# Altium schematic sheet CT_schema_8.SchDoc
size 277 x 170 mm
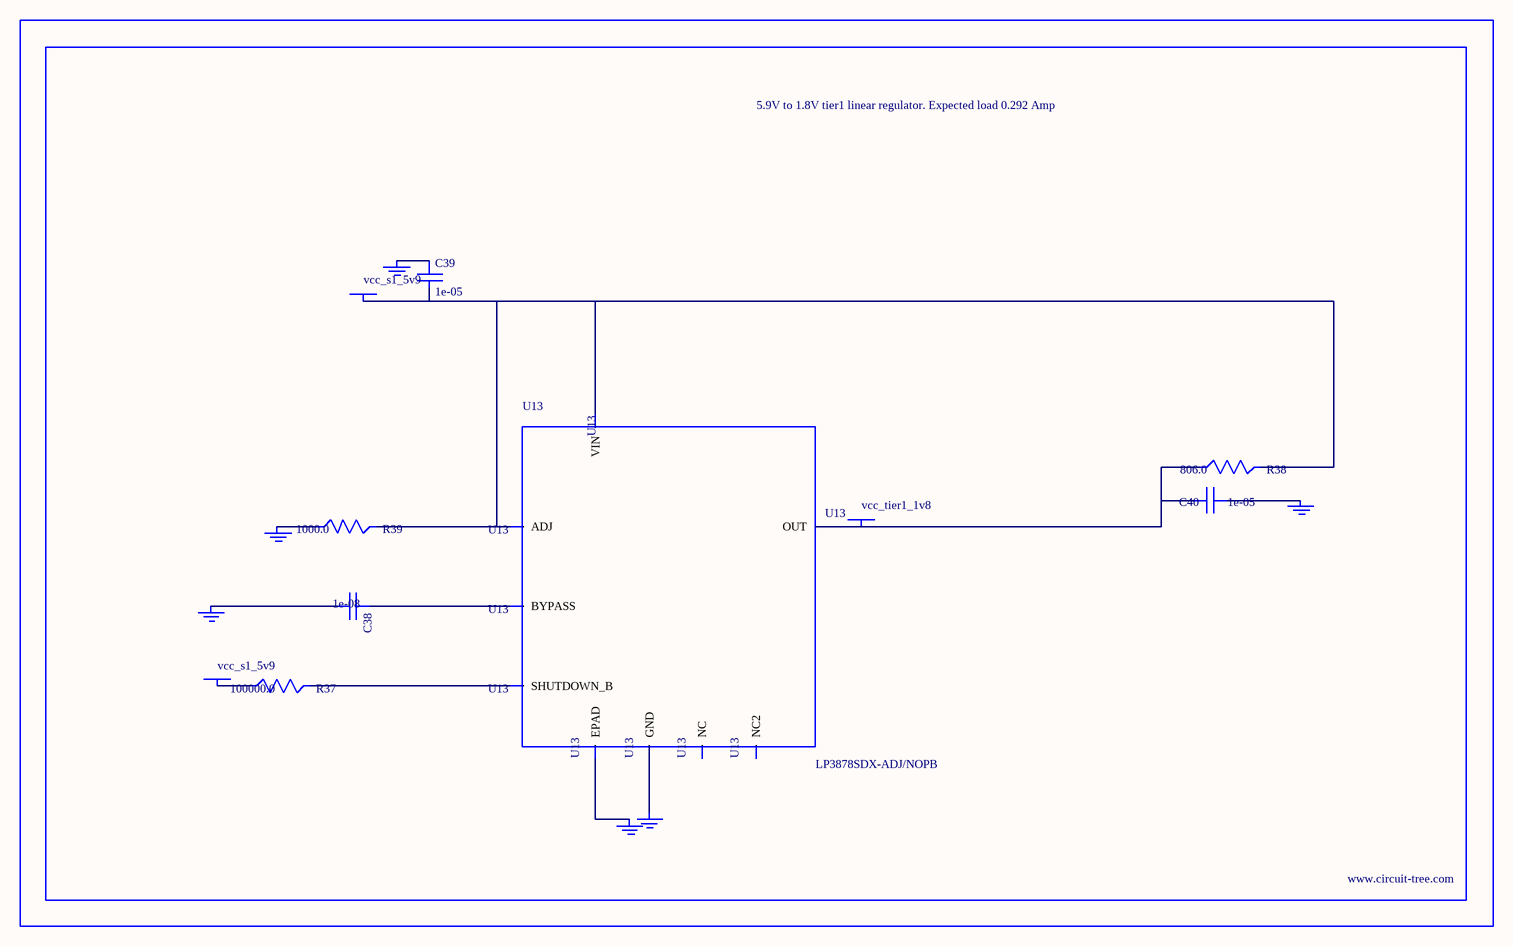
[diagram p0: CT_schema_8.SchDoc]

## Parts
BORDER7  (no value)
C38  1e-08  [C0402]
C39  1e-05  [C1206]
C40  1e-05  [C0805]
GND_INSTANCE_7_0  (no value)
GND_INSTANCE_7_1  (no value)
GND_INSTANCE_7_2  (no value)
GND_INSTANCE_7_3  (no value)
GND_INSTANCE_7_4  (no value)
GND_INSTANCE_7_5  (no value)
POWER_INSTANCE_7_0  vcc_s1_5v9
POWER_INSTANCE_7_1  vcc_s1_5v9
POWER_INSTANCE_7_2  vcc_tier1_1v8
R37  100000.0  [R0603]
R38  806.0  [R0603]
R39  1000.0  [R0603]
U13  LP3878SDX-ADJ/NOPB  [WSON-8]

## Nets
NetC38_1: C38.1 U13.1(BYPASS)
NetC38_2: C38.2 GND_INSTANCE_7_0.0(GND)
NetC39_1: C39.1 GND_INSTANCE_7_1.0(GND)
NetC39_2: C39.2 POWER_INSTANCE_7_0.0(PWR) R38.2 R39.2 U13.4(VIN) U13.6(ADJ)
NetC40_1: C40.1 GND_INSTANCE_7_2.0(GND)
NetC40_2: C40.2 POWER_INSTANCE_7_2.0(PWR) R38.1 U13.5(OUT)
NetGND_INSTANCE_7_3_0: GND_INSTANCE_7_3.0(GND) R39.1
NetGND_INSTANCE_7_4_0: GND_INSTANCE_7_4.0(GND) U13.PAD(EPAD)
NetGND_INSTANCE_7_5_0: GND_INSTANCE_7_5.0(GND) U13.3(GND)
NetPOWER_INSTANCE_7_1_0: POWER_INSTANCE_7_1.0(PWR) R37.1
NetR37_2: R37.2 U13.8(SHUTDOWN_B)

Not connected (* = marked no-connect by the designer): U13 2(NC) 7(NC2)

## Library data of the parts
BORDER7 = BORDER_PAGE7
C38 = C0402C103K3RAC
C39 = C1206C106K3RACTU
C40 = GRM219R60J106ME19D
GND_INSTANCE_7_0-GND_INSTANCE_7_5 = GND
POWER_INSTANCE_7_0-POWER_INSTANCE_7_2 = PWR
R37 = RC0603JR-07100KL
R38 = ERJ-3EKF8060V
R39 = RC0603JR-071KL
